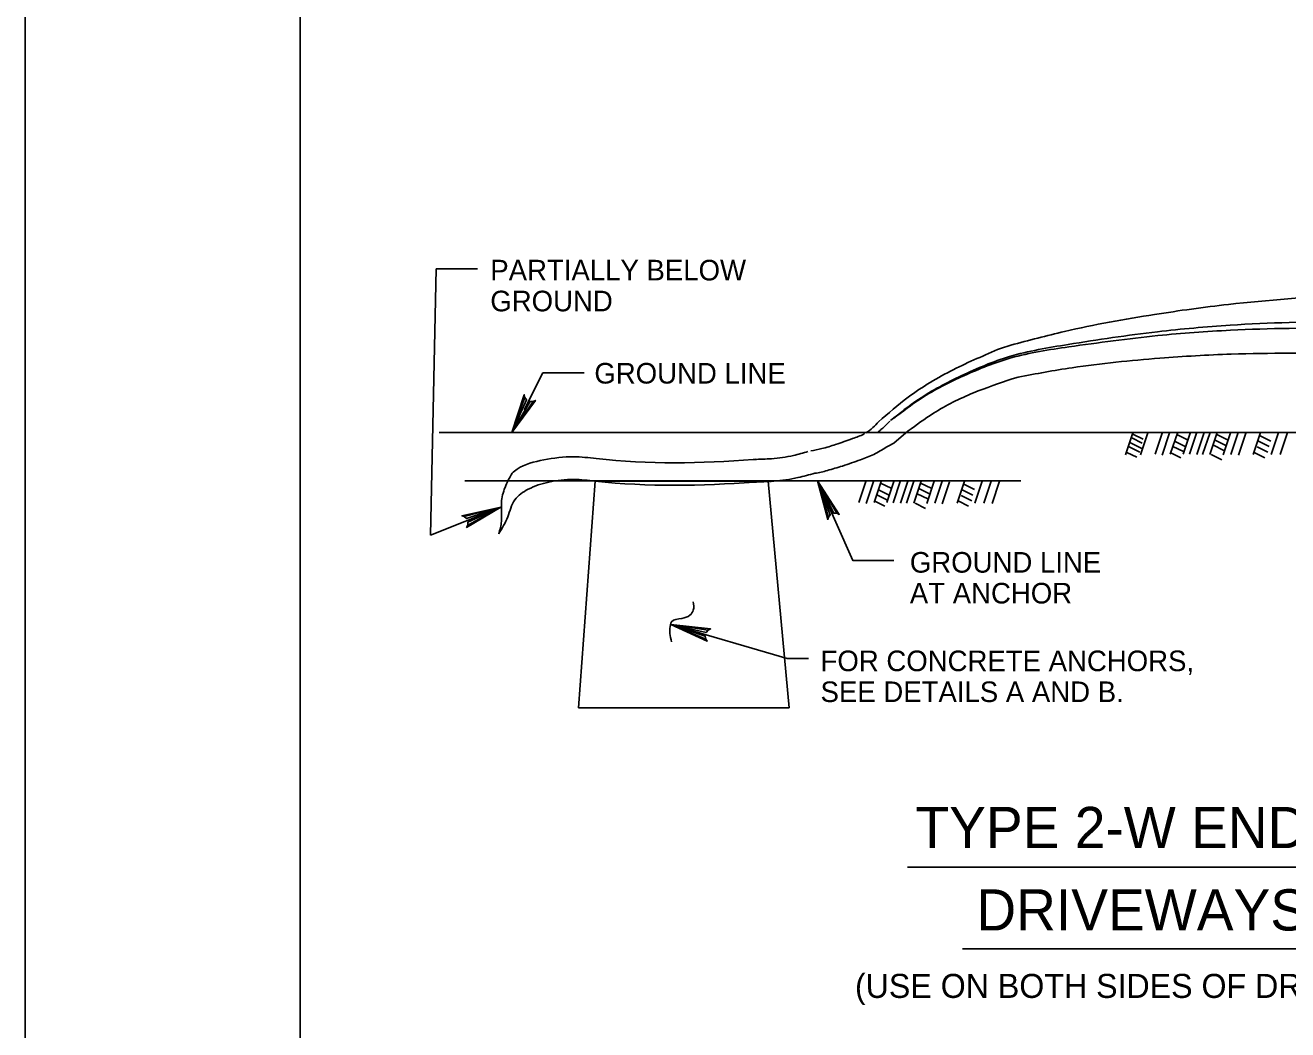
# Model space of a CAD drawing. Extents: x 637628 to 640188, y 298266 to 300751.
# Drawn here: x 638278.5 to 638462.3, y 298411.9 to 298558.2 of the extents above; entities that cross this region are included whole.
import ezdxf

# ---------------------------------------------------------------- set-up
doc = ezdxf.new("R2010")
doc.units = 0
for name, color, linetype in [('1', 7, 'Continuous'), ('2', 7, 'Continuous'), ('3', 7, 'Continuous'), ('PLT-BNDY', 7, 'Continuous')]:
    doc.layers.add(name, color=color, linetype=linetype)

msp = doc.modelspace()

# ---------------------------------------------------------------- linework, layer by layer
at = {"layer": '1'}
msp.add_lwpolyline([(639104.52, 298280.58), (639104.52, 298844.55), (638318.55, 298844.55), (638318.55, 298280.58), (639104.52, 298280.58), (639104.52, 298306.93), (638904.53, 298306.93), (638904.53, 298371.61), (639104.52, 298371.61), (639104.52, 298400.57), (638904.53, 298400.57), (638904.53, 298280.58), (638983.33, 298280.58), (638983.33, 298306.93), (638983.33, 298280.58), (639060.33, 298280.58), (639060.33, 298306.93), (639060.33, 298294.62), (639104.52, 298294.62)], dxfattribs=at)
at = {"layer": '2'}
for p, q in [((638337.51, 298483.92), (638338.36, 298522.7)), ((638420.51, 298511.12), (638422.02, 298511.59)), ((638422.2, 298506.67), (638423.1, 298506.95)), ((638338.78, 298498.88), (638634.69, 298498.88)), ((638407.06, 298499.09), (638404.97, 298497.33)), ((638439.79, 298498.83), (638438.72, 298495.61)), ((638439.79, 298498.65), (638441.3, 298497.89)), ((638441.97, 298498.83), (638440.9, 298495.61)), ((638444.08, 298498.94), (638443.01, 298495.73)), ((638445.12, 298498.81), (638444.05, 298495.59)), ((638446.31, 298498.94), (638445.23, 298495.73)), ((638448.17, 298498.94), (638447.1, 298495.73)), ((638449.08, 298498.94), (638448, 298495.73)), ((638450.15, 298498.88), (638449.08, 298495.66)), ((638451.01, 298498.88), (638449.93, 298495.66)), ((638452.06, 298498.88), (638450.99, 298495.66)), ((638453.99, 298498.83), (638452.92, 298495.61)), ((638455.12, 298498.87), (638454.05, 298495.66)), ((638456.22, 298498.76), (638455.14, 298495.55)), ((638458.38, 298498.88), (638457.31, 298495.66)), ((638460.98, 298498.88), (638459.91, 298495.66)), ((638462.27, 298498.88), (638461.2, 298495.66)), ((638439.36, 298497.41), (638441.17, 298496.51)), ((638439.61, 298498.08), (638441.12, 298497.33)), ((638445.61, 298496.85), (638447.16, 298496.08)), ((638445.86, 298497.59), (638447.4, 298496.82)), ((638446.17, 298498.58), (638447.72, 298497.81)), ((638451.5, 298497.03), (638453.04, 298496.26)), ((638451.75, 298497.77), (638453.29, 298497)), ((638452, 298498.58), (638453.54, 298497.81)), ((638458.06, 298497.59), (638459.61, 298496.82)), ((638458.31, 298498.4), (638459.85, 298497.63)), ((638438.92, 298495.97), (638440.34, 298495.26)), ((638439.23, 298496.78), (638440.77, 298496.01)), ((638445.23, 298495.97), (638446.78, 298495.2)), ((638451.19, 298495.66), (638452.73, 298494.89)), ((638457.44, 298495.97), (638458.98, 298495.2)), ((638457.88, 298496.78), (638459.43, 298496.01)), ((638342.5, 298491.81), (638423.47, 298491.81)), ((638359.08, 298458.79), (638361.5, 298491.78)), ((638361.5, 298491.78), (638386.68, 298491.78)), ((638386.68, 298491.78), (638389.73, 298458.79)), ((638400.96, 298491.87), (638399.89, 298488.66)), ((638402, 298491.74), (638400.93, 298488.52)), ((638403.19, 298491.87), (638402.12, 298488.66)), ((638403.06, 298491.51), (638404.6, 298490.74)), ((638405.05, 298491.87), (638403.98, 298488.66)), ((638405.96, 298491.87), (638404.89, 298488.65)), ((638407.03, 298491.8), (638405.96, 298488.59)), ((638407.89, 298491.8), (638406.82, 298488.59)), ((638408.94, 298491.8), (638407.87, 298488.59)), ((638408.88, 298491.51), (638410.42, 298490.74)), ((638410.87, 298491.76), (638409.8, 298488.54)), ((638412, 298491.8), (638410.93, 298488.59)), ((638413.1, 298491.69), (638412.03, 298488.47)), ((638415.26, 298491.8), (638414.19, 298488.59)), ((638415.19, 298491.33), (638416.74, 298490.55)), ((638417.86, 298491.8), (638416.79, 298488.59)), ((638419.15, 298491.8), (638418.08, 298488.59)), ((638420.34, 298491.76), (638419.27, 298488.54)), ((638402.49, 298489.78), (638404.04, 298489)), ((638402.74, 298490.52), (638404.29, 298489.75)), ((638408.38, 298489.96), (638409.93, 298489.19)), ((638408.63, 298490.7), (638410.17, 298489.93)), ((638414.76, 298489.71), (638416.31, 298488.94)), ((638414.95, 298490.52), (638416.49, 298489.75)), ((638402.12, 298488.9), (638403.66, 298488.13)), ((638408.07, 298488.59), (638409.61, 298487.82)), ((638414.32, 298488.9), (638415.86, 298488.13)), ((638389.73, 298458.79), (638359.08, 298458.79))]:
    msp.add_line(p, q, dxfattribs=at)
for points in [[(638344.36, 298522.7), (638338.36, 298522.7)], [(638359.89, 298507.54), (638353.89, 298507.54), (638351.14, 298502.15)], [(638352.45, 298503.4), (638352.01, 298503.4), (638349.37, 298498.86), (638352.45, 298503.4), (638352.79, 298503.54), (638349.37, 298498.86), (638351.52, 298503.65), (638351.26, 298503.99), (638349.37, 298498.86), (638351.16, 298504.38), (638351.26, 298503.99)], [(638404.99, 298480.25), (638398.99, 298480.25), (638393.88, 298491.81)], [(638395.46, 298486.55), (638395.73, 298486.89), (638393.88, 298491.81), (638395.46, 298486.55), (638395.35, 298486.2), (638393.88, 298491.81), (638396.23, 298487.12), (638396.67, 298487.1), (638393.88, 298491.81), (638397.03, 298486.94), (638396.67, 298487.1)], [(638337.51, 298483.92), (638347.75, 298488.02)], [(638342.44, 298486.63), (638342.78, 298486.34), (638347.75, 298488.02), (638342.44, 298486.63), (638342.09, 298486.74), (638347.75, 298488.02), (638342.98, 298485.83), (638342.95, 298485.39), (638347.75, 298488.02), (638342.77, 298485.04), (638342.95, 298485.39)], [(638377.61, 298468.79), (638377.51, 298469.23), (638372.53, 298470.89), (638377.61, 298468.79), (638377.81, 298468.49), (638372.53, 298470.89), (638377.65, 298469.76), (638377.94, 298470.08), (638372.53, 298470.89), (638378.29, 298470.26), (638377.94, 298470.08)], [(638392.56, 298465.97), (638389.43, 298465.97), (638372.53, 298470.89)]]:
    msp.add_lwpolyline(points, dxfattribs=at)
for points in [[(638471, 298518.96), (638453.71, 298517.53), (638442.95, 298516.06), (638429.84, 298513.59), (638422.02, 298511.59)], [(638471.09, 298515.13), (638453.96, 298514.5), (638443.34, 298513.54), (638430.34, 298511.69), (638421.81, 298509.92), (638414.88, 298507.17), (638408.57, 298503.69), (638404.49, 298500.62)], [(638471.09, 298514.14), (638454, 298513.77), (638443.42, 298512.98), (638430.45, 298511.34), (638422.01, 298509.73), (638415.18, 298507.14), (638408.94, 298503.83), (638404.93, 298500.9)], [(638420.51, 298511.12), (638413.64, 298508.02), (638407.06, 298504), (638402.74, 298500.43)], [(638471, 298510.35), (638454.11, 298510.29), (638443.71, 298509.69), (638430.93, 298508.31), (638423.1, 298506.95)], [(638422.2, 298506.67), (638416.57, 298504.64), (638410.73, 298501.67), (638407.06, 298499.09)], [(638404.41, 298500.53), (638403.23, 298499.39), (638402.7, 298498.99)], [(638400.73, 298498.71), (638400.62, 298498.65), (638398.95, 298497.98), (638396.5, 298497.12), (638394.49, 298496.53), (638392.87, 298496.19)], [(638400.73, 298498.71), (638400.62, 298498.65), (638398.95, 298497.98), (638396.5, 298497.12), (638394.49, 298496.53), (638392.87, 298496.19)], [(638402.74, 298500.43), (638401.93, 298499.58), (638400.89, 298498.8)], [(638404.97, 298497.33), (638403.88, 298496.72), (638402.06, 298495.68), (638400.11, 298494.9), (638397.51, 298493.99), (638395.3, 298493.34), (638393.48, 298492.95), (638393.46, 298492.95)], [(638384.9, 298494.97), (638384.52, 298494.94), (638361.65, 298495.07), (638358.34, 298495.35), (638354.02, 298494.88), (638350.14, 298493.53), (638349.39, 298492.94)], [(638384.9, 298494.97), (638384.52, 298494.94), (638361.65, 298495.07), (638358.34, 298495.35), (638354.02, 298494.88), (638350.14, 298493.53), (638349.39, 298492.94)], [(638392.48, 298496.09), (638390.35, 298495.53), (638387.18, 298495.06), (638384.66, 298494.95)], [(638392.48, 298496.09), (638390.35, 298495.53), (638387.18, 298495.06), (638384.66, 298494.95)], [(638349.39, 298492.94), (638348.37, 298490.87), (638347.85, 298488.66), (638347.85, 298485.93), (638347.46, 298484.11)], [(638385.29, 298491.7), (638384.64, 298491.65), (638361.5, 298491.78), (638358.38, 298492.04), (638354.74, 298491.65), (638351.75, 298490.61), (638349.8, 298489.05), (638348.76, 298486.58), (638347.46, 298484.11)], [(638393.48, 298492.95), (638391.01, 298492.3), (638387.5, 298491.78), (638384.64, 298491.65)], [(638372.63, 298468.39), (638372.39, 298469.6), (638372.39, 298470.33), (638372.63, 298471.3), (638374.09, 298471.79), (638375.3, 298472.27), (638375.78, 298473), (638375.78, 298474.21)]]:
    msp.add_spline(points, degree=3, dxfattribs=at)
at = {"layer": '3'}
for p, q in [((638406.98, 298435.58), (638545.08, 298435.58)), ((638414.99, 298423.66), (638536.25, 298423.66))]:
    msp.add_line(p, q, dxfattribs=at)
at = {"layer": 'PLT-BNDY'}
msp.add_lwpolyline([(638278.52, 298859.58), (639119.52, 298859.58), (639119.52, 298265.58), (638278.52, 298265.58)], close=True, dxfattribs=at)

# ---------------------------------------------------------------- texts
at = {"layer": '3'}
for s, height, p in [('PARTIALLY BELOW', 2.9999, (638346.23, 298521.02)), ('GROUND', 3, (638346.23, 298516.52)), ('GROUND LINE', 2.9999, (638361.38, 298506)), ('GROUND LINE', 2.9999, (638407.31, 298478.46)), ('AT ANCHOR', 3, (638407.31, 298473.97)), ('FOR CONCRETE ANCHORS,', 2.9999, (638394.31, 298464.11)), ('SEE DETAILS A AND B.', 2.9999, (638394.31, 298459.61)), ('TYPE 2-W END TREATMENT,', 6, (638408.13, 298438.34)), ('DRIVEWAYS & OPENINGS', 6, (638416.99, 298426.34)), ('(USE ON BOTH SIDES OF DRIVEWAYS & OPENINGS)', 3.5, (638399.32, 298416.52))]:
    msp.add_text(s, height=height, dxfattribs=at).set_placement(p)

doc.saveas('drawing.dxf')
